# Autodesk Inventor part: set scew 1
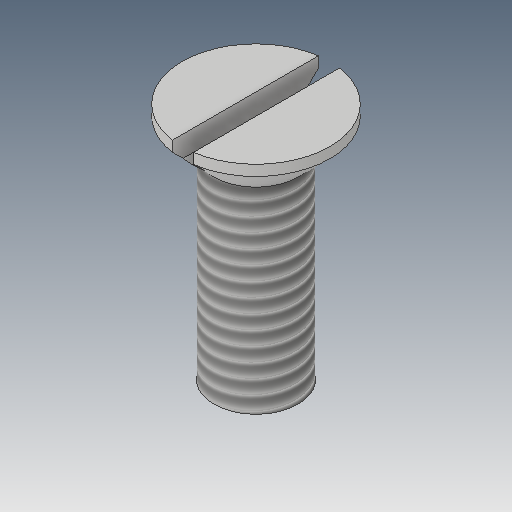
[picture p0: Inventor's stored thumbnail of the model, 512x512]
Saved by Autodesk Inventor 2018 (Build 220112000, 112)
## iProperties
Created: 2016-06
Part Number: set scew 1
Material: Generic
Document SubType Name: Modeling
Designer: CADCIM
Density: 1 g/cm^3
Appearance: Default
Author: CADCIM
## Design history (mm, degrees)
sketch "Sketch1"
  geometry: C1 r 3 at (0, 0); 1 further point
  constraints: 1 centre point, 1 coincident
  dimensions: "d0" = 6 diameter of C1
extrude "Extrusion1" new body sketch "Sketch1" distance "d1" = 14; taper "d2" = 0 deg
sketch "Sketch2"
  geometry: L1 (14, -3)-(14, 3) reference; L2 (14, 0)-(14, -3); L3 (14, -3)-(17, -6); L4 (17, -6)-(17, 0); L5 (17, 0)-(14, 0); 1 further point
  constraints: 8 end point, 2 vertical, 1 midpoint, 1 perpendicular
  dimensions: "d4" = 3 distance of L2.start L2.end; "d5" = 6 distance of L4.end L3.end; "d6" = 3 distance from line of L1.start L4
revolve "Revolution1" sketch "Sketch2" stored, may be unused: angle "d7" = 90 deg
sketch "Sketch3"
  geometry: C1 r 5.25 at (0, 0); 1 further point
  constraints: 1 centre point, 1 coincident
  dimensions: "d8" = 10.5 diameter of C1
extrude "Extrusion2" sketch "Sketch3" distance "d9" = 26.75; taper "d10" = 0 deg
sketch "Sketch4"
  geometry: L1 (-0.75, 8.347)-(0.75, 8.347); L2 (0.75, 8.347)-(0.75, -8.125); L3 (0.75, -8.125)-(-0.75, -8.125); L4 (-0.75, -8.125)-(-0.75, 8.347); L5 (0, 0)-(0, 6.165)
  constraints: 10 end point, 3 parallel, 1 horizontal, 1 perpendicular, 1 other
  dimensions: "d11" = 1.5 distance of L1.start L1.end
extrude "Extrusion3" cut sketch "Sketch4" distance "d12" = 1.5; taper "d13" = 0 deg
sketch "Sketch5"
  geometry: L1 (0, 0)-(0, 3); L2 (0, 3)-(-1.732, 0); L3 (-1.732, 0)-(0, 0); L4 (0, 3)-(0, -3) reference; 1 further point
  constraints: 6 end point, 2 midpoint, 1 perpendicular, 1 point on line, 1 vertical
  dimensions: "d21" = 60 deg angle of L2 L3; "d22" = 3 distance of L1.start L1.end
thread "Thread2" dims "d19" = 10, "d20" = 0
revolve "Revolution3" stored, may be unused: angle "d23" = 90 deg
body "Solid1"
